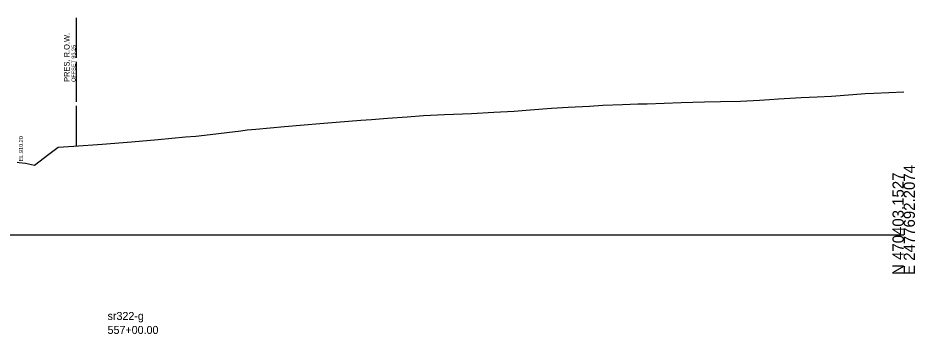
# Model space of a CAD drawing. Extents: x -26 to 4781, y -31 to 24738.
# Drawn here: x 2378.6 to 2602.8, y 7475.2 to 7554.3 of the extents above; entities that cross this region are included whole.
import ezdxf

# ---------------------------------------------------------------- set-up
doc = ezdxf.new("R2010")
doc.units = 0
for name, color, linetype in [('DESIGN - SHEET - Light Grid', 7, 'Continuous'), ('DESIGN - TYPICAL - Warning Text', 7, 'Continuous'), ('SURVEY - GROUND - Existing Pavement Text', 7, 'Continuous'), ('SURVEY - GROUND - Top of Ground', 7, 'Continuous'), ('SURVEY - PROPERTY - ROW Lines', 7, 'Continuous'), ('SURVEY - PROPERTY - ROW Lines Text', 7, 'Continuous')]:
    doc.layers.add(name, color=color, linetype=linetype)

msp = doc.modelspace()

# ---------------------------------------------------------------- linework, layer by layer
at = {"layer": 'DESIGN - SHEET - Light Grid'}
msp.add_line((2300, 7500), (2600, 7500), dxfattribs=at)
at = {"layer": 'SURVEY - GROUND - Top of Ground'}
msp.add_lwpolyline([(2378.4, 7518.16), (2378.87, 7518.14), (2380.47, 7517.95), (2382.74, 7517.42), (2386.33, 7520.2), (2388.66, 7521.93), (2392.55, 7522.2), (2399.67, 7522.72), (2407.02, 7523.27), (2413.65, 7523.87), (2420.47, 7524.5), (2423.05, 7524.73), (2425.25, 7524.94), (2434.35, 7526.02), (2435.93, 7526.25), (2438.06, 7526.44), (2445.25, 7527.11), (2449.16, 7527.45), (2455.07, 7527.94), (2464.28, 7528.66), (2466.95, 7528.89), (2470.94, 7529.17), (2475.92, 7529.49), (2479.95, 7529.83), (2485.21, 7530.09), (2491.95, 7530.33), (2497.54, 7530.67), (2502.62, 7530.98), (2506.6, 7531.29), (2512, 7531.67), (2516.09, 7531.95), (2521.45, 7532.22), (2524.78, 7532.41), (2529.74, 7532.6), (2533.57, 7532.76), (2535.88, 7532.81), (2544.41, 7533.11), (2550.21, 7533.25), (2554.22, 7533.36), (2559.21, 7533.48), (2563.94, 7533.69), (2566.47, 7533.88), (2568.68, 7534), (2574.41, 7534.34), (2578.34, 7534.52), (2581.96, 7534.73), (2587.32, 7535.14), (2590.34, 7535.34), (2592.56, 7535.47), (2600, 7535.79)], dxfattribs=at)
at = {"layer": 'SURVEY - PROPERTY - ROW Lines'}
for p, q in [((2393.25, 7544.25), (2393.25, 7554.25)), ((2393.25, 7533.25), (2393.25, 7543.25)), ((2393.25, 7522.25), (2393.25, 7532.25))]:
    msp.add_line(p, q, dxfattribs=at)

# ---------------------------------------------------------------- texts
at = {"layer": 'DESIGN - SHEET - Light Grid'}
for s, p in [('E 2477692.2074', (2602.8, 7490)), ('N 470403.1527', (2600, 7490))]:
    msp.add_text(s, height=2.8, rotation=90, dxfattribs=at).set_placement(p)
at = {"layer": 'DESIGN - TYPICAL - Warning Text'}
for s, p in [('sr322-g', (2401, 7478.75)), ('557+00.00', (2401, 7475.25))]:
    msp.add_text(s, height=2, dxfattribs=at).set_placement(p)
at = {"layer": 'SURVEY - GROUND - Existing Pavement Text'}
msp.add_text('EL.910.20', height=1, rotation=90, dxfattribs=at).set_placement((2379.85, 7518.4))
at = {"layer": 'SURVEY - PROPERTY - ROW Lines Text'}
for s, height, p in [('PRES. R.O.W.', 1.4, (2391.5, 7538.25)), ('OFFSET 93.25', 1, (2393, 7538.25))]:
    msp.add_text(s, height=height, rotation=90, dxfattribs=at).set_placement(p)

doc.saveas('drawing.dxf')
